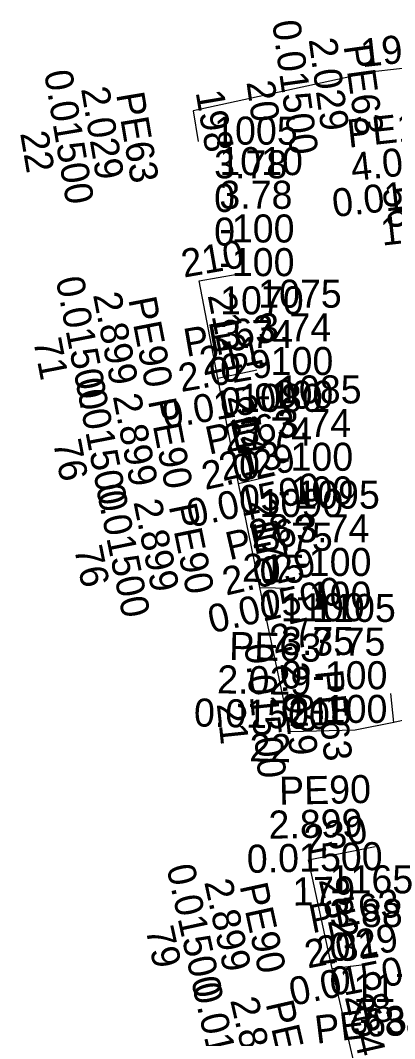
# Model space of a CAD drawing. Extents: x 607463 to 609569, y 4065893 to 4067650.
# Drawn here: x 607463 to 607729, y 4066739 to 4067465 of the extents above; entities that cross this region are included whole.
import ezdxf

# ---------------------------------------------------------------- set-up
doc = ezdxf.new("R2010")
doc.units = 0
for name, color, linetype in [('GW_NATT', 7, 'Continuous'), ('GW_NODETX', 7, 'Continuous'), ('GW_PATT', 7, 'Continuous'), ('PE125', 7, 'Continuous'), ('PE63', 7, 'Continuous'), ('PE90', 7, 'Continuous')]:
    doc.layers.add(name, color=color, linetype=linetype)

msp = doc.modelspace()

# ---------------------------------------------------------------- linework, layer by layer
at = {"layer": 'PE125'}
msp.add_lwpolyline([(607747.12, 4067432), (607713.38, 4067428.25), (607585.5, 4067400.25)], dxfattribs=at)
at = {"layer": 'PE63'}
for p, q in [((607585.5, 4067400.25), (607589.19, 4067378.5)), ((607589.75, 4067279.25), (607616.81, 4067284)), ((607603.25, 4067209.75), (607630.94, 4067215.75)), ((607617.88, 4067134.75), (607643.94, 4067140.75)), ((607633.06, 4067060.5), (607655.31, 4067060)), ((607728.44, 4066964.25), (607726.25, 4066985)), ((607667.69, 4066866.5), (607715.19, 4066876)), ((607684.62, 4066789), (607713, 4066792.5))]:
    msp.add_line(p, q, dxfattribs=at)
at = {"layer": 'PE90'}
for p, q in [((607603.25, 4067209.75), (607589.75, 4067279.25)), ((607617.88, 4067134.75), (607603.25, 4067209.75)), ((607633.06, 4067060.5), (607617.88, 4067134.75)), ((607684.62, 4066789), (607667.69, 4066866.5)), ((607705.12, 4066699.75), (607684.62, 4066789))]:
    msp.add_line(p, q, dxfattribs=at)
for points in [[(607728.44, 4066964.25), (607700.81, 4066958.75), (607654.75, 4066957.75), (607633.06, 4067060.5)], [(607913.69, 4067015.25), (607880.12, 4066998.75), (607728.44, 4066964.25)]]:
    msp.add_lwpolyline(points, dxfattribs=at)

# ---------------------------------------------------------------- texts
at = {"layer": 'GW_NATT'}
for s, p in [('3.78 ', (607600.5, 4067352.25)), ('3.78 ', (607604.19, 4067330.5)), ('0 ', (607600.5, 4067328.25)), ('0 ', (607600.5, 4067304.25)), ('-100 ', (607604.19, 4067306.5)), ('-100 ', (607604.19, 4067282.5)), ('3.74 ', (607604.75, 4067231.25)), ('3.74 ', (607631.81, 4067236)), ('0 ', (607604.75, 4067207.25)), ('-100 ', (607631.81, 4067212)), ('-100 ', (607631.81, 4067188)), ('0 ', (607604.75, 4067183.25)), ('3.74 ', (607645.94, 4067167.75)), ('3.74 ', (607618.25, 4067161.75)), ('-100 ', (607645.94, 4067143.75)), ('0 ', (607618.25, 4067137.75)), ('0 ', (607618.25, 4067113.75)), ('-100 ', (607645.94, 4067119.75)), ('3.74 ', (607658.94, 4067092.75)), ('3.75 ', (607632.88, 4067086.75)), ('0 ', (607632.88, 4067062.75)), ('-100 ', (607658.94, 4067068.75)), ('-100 ', (607658.94, 4067044.75)), ('0 ', (607632.88, 4067038.75)), ('3.75 ', (607648.06, 4067012.5)), ('3.75 ', (607670.31, 4067012)), ('0 ', (607648.06, 4066988.5)), ('-100 ', (607670.31, 4066988)), ('0 ', (607648.06, 4066964.5)), ('-100 ', (607670.31, 4066964)), ('3.88 ', (607682.69, 4066818.5)), ('0 ', (607682.69, 4066794.5)), ('0 ', (607682.69, 4066770.5)), ('3.88 ', (607699.62, 4066741))]:
    msp.add_text(s, height=20, dxfattribs=at).set_placement(p)
at = {"layer": 'GW_NODETX'}
for s, p in [('1005', (607600.5, 4067376.25)), ('1010', (607604.19, 4067354.5)), ('1075', (607631.81, 4067260)), ('1070', (607604.75, 4067255.25)), ('1080', (607618.25, 4067185.75)), ('1085', (607645.94, 4067191.75)), ('1095', (607658.94, 4067116.75)), ('1090', (607632.88, 4067110.75)), ('1100', (607648.06, 4067036.5)), ('1105', (607670.31, 4067036)), ('1165', (607682.69, 4066842.5)), ('1175', (607699.62, 4066765))]:
    msp.add_text(s, height=20, dxfattribs=at).set_placement(p)
at = {"layer": 'GW_PATT'}
for s, rotation, p in [('0.01500', 277.93, (607641.73, 4067463.8)), ('199', 6.34, (607705.96, 4067431.45)), ('2.029', 277.93, (607667.71, 4067451.26)), ('PE63', 277.93, (607692.58, 4067446.65)), ('0.01500', 279.62, (607479.39, 4067427.87)), ('2.029', 279.62, (607505.73, 4067416.11)), ('20', 277.93, (607623.48, 4067420.87)), ('PE63', 279.62, (607530.73, 4067412.23)), ('198', 279.62, (607587.28, 4067413.71)), ('PE125', 6.34, (607696.24, 4067374.03)), ('22', 279.62, (607462.41, 4067384.42)), ('4.026', 6.34, (607698.89, 4067350.17)), ('0.01500', 6.34, (607685.64, 4067324.55)), ('56', 280.93, (607719.9, 4067344.44)), ('165', 6.34, (607720.09, 4067304.23)), ('210', 9.96, (607578.95, 4067281.42)), ('0.01500', 280.99, (607487.66, 4067280.4)), ('2.899', 280.99, (607514.27, 4067269.27)), ('PE90', 280.99, (607539.35, 4067266)), ('212', 280.99, (607595.85, 4067268.82)), ('PE63', 9.96, (607580.75, 4067224.88)), ('71', 280.99, (607471.72, 4067236.56)), ('211', 12.23, (607592.79, 4067211.58)), ('2.029', 9.96, (607577.02, 4067199.85)), ('0.01500', 281.03, (607501.69, 4067208.08)), ('0.01500', 9.96, (607565.41, 4067173.45)), ('2.899', 281.03, (607528.31, 4067196.96)), ('PE90', 281.03, (607553.4, 4067193.71)), ('214', 281.03, (607609.9, 4067196.57)), ('PE63', 12.23, (607596.83, 4067155.15)), ('27', 9.96, (607608.96, 4067156.73)), ('76', 281.03, (607485.79, 4067164.22)), ('2.029', 12.23, (607594.1, 4067130)), ('213', 12.96, (607606.62, 4067136.26)), ('0.01500', 12.23, (607583.54, 4067103.16)), ('0.01500', 281.56, (607516.28, 4067132.45)), ('2.899', 281.56, (607542.99, 4067121.58)), ('PE90', 281.56, (607568.11, 4067118.56)), ('217', 281.56, (607624.58, 4067121.94)), ('PE63', 12.96, (607611.39, 4067079.9)), ('28', 12.23, (607627.72, 4067088.17)), ('76', 281.56, (607500.78, 4067088.45)), ('2.029', 12.96, (607608.98, 4067054.71)), ('215', 358.71, (607620.28, 4067064.79)), ('0.01500', 12.96, (607598.77, 4067027.74)), ('27', 12.96, (607643.13, 4067013.32)), ('PE63', 358.71, (607611.03, 4067008.98)), ('0.01500', 276.02, (607622.02, 4067019.83)), ('2.029', 358.71, (607602.49, 4066985.17)), ('2.029', 276.02, (607647.57, 4067006.44)), ('PE63', 276.02, (607672.28, 4067001)), ('0.01500', 358.71, (607585.96, 4066961.53)), ('218', 1.24, (607653.7, 4066961.73)), ('21', 276.02, (607602.35, 4066977.54)), ('22', 358.71, (607625.41, 4066936.64)), ('PE90', 1.24, (607646.92, 4066905.57)), ('2.899', 1.24, (607639.44, 4066881.4)), ('230', 11.31, (607667.12, 4066870.47)), ('0.01500', 1.24, (607623.96, 4066857.06)), ('0.01500', 282.33, (607566.51, 4066861.11)), ('2.899', 282.33, (607593.37, 4066850.6)), ('PE90', 282.33, (607618.52, 4066847.91)), ('179', 1.24, (607656.48, 4066833.76)), ('232', 282.33, (607674.94, 4066852.05)), ('PE63', 11.31, (607670.26, 4066813.98)), ('2.029', 11.31, (607667.12, 4066788.88)), ('79', 282.33, (607551.6, 4066816.91)), ('231', 7.03, (607674.5, 4066791.78)), ('0.01500', 11.31, (607656.14, 4066762.21)), ('0.01500', 282.94, (607584.88, 4066776.57)), ('234', 282.94, (607693.4, 4066768.66)), ('48', 11.31, (607700.07, 4066746.52)), ('2.899', 282.94, (607611.85, 4066766.35)), ('PE90', 282.94, (607637.03, 4066763.92)), ('PE63', 7.03, (607673.42, 4066735.22))]:
    msp.add_text(s, height=20, rotation=rotation, dxfattribs=at).set_placement(p)

doc.saveas('drawing.dxf')
